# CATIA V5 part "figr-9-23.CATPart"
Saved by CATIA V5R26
Part number: Part2
Bounding box of the stored display mesh (mm): x -72 to 72, y -80 to 90, z -20 to 41.296
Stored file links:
  D:\_Deepak\CATIA\CATIA V5-6R2016_Deepak\Resources\Part files\Partfiles\c09_catia_v5_6r2016_prt\figr-9-23.CATPart
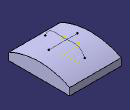
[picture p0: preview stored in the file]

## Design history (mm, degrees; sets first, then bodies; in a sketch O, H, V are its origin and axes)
Body1 (main body)
  Sketch1 on yz-plane, origin (0, 0, 0), H (0, 1, 0), V (0, 0, 1)
    arc A1 centre (5, -170) radius 190.0658 from (-80, 0) to (90, 0) cw
    point P2 (-80, 0)
    point P3 (0, 20)
    line L1 (-80, 0) -> (-80, -20)
    line L2 (-80, -20) -> (90, -20)
    line L3 (90, -20) -> (90, 0)
    coincidence: P2 H, A1 P3, P3 V
    vertical: L1 V, L3 V
    horizontal: L2 H
  Pad1: profile Sketch1, direction (1, 0, 0), length 72, mirrored extent
  Sketch2 on zx-plane, origin (0, 0, 0), H (-1, 0, 0), V (0, 0, 1)
    line L1 (-40, 30) -> (40, 30)
    horizontal: L1 H
  Sketch3 on yz-plane, origin (0, 0, 0), H (0, 1, 0), V (0, 0, 1)
    spline S1 through (60, 20) (40, 40) (10, 40) (-10, 40) (-30, 40) (-50, 20)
